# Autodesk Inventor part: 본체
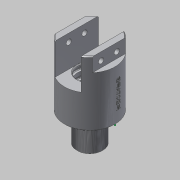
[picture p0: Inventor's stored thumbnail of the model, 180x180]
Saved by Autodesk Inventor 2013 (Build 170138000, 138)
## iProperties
Created: 2019-02
Part Number: 본체
Material: 알루미늄 6061
Document SubType Name: Modeling
Designer: Gpr
Density: 1 g/cm^3
Author: Gpr
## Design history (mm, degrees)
sketch "스케치1"
  geometry: C1 r 29 at (0, 0)
  constraints: 1 centre point
  dimensions: "d0" = 58 diameter of C1
extrude "돌출1" new body sketch "스케치1" distance "d1" = 74; taper "d2" = 0 deg
chamfer "모따기1" distance "d3" = 1; stored, may be unused: second distance "d4" = 2, angle "d5" = 45 deg
sketch "스케치2"
  geometry: C1 r 28 at (0, 0) reference; C2 r 13 at (0, 0)
  constraints: 1 centre point, 1 coincident
  dimensions: "d6" = 26 diameter of C2
extrude "돌출2" join sketch "스케치2" distance "d7" = 5; taper "d8" = 0 deg
sketch "스케치3"
  geometry: C1 r 13 at (0, 0) reference; C2 r 15 at (0, 0)
  constraints: 1 centre point, 1 coincident
  dimensions: "d9" = 30 diameter of C2
extrude "돌출3" join sketch "스케치3" distance "d10" = 28; taper "d11" = 0 deg
chamfer "모따기2" distance "d12" = 1; stored, may be unused: second distance "d13" = 2, angle "d14" = 45 deg
feature "스레드1" dims "d15" = 10, "d16" = 0
sketch "스케치4"
  geometry: L1 (-15, 29)-(15, 29); L2 (22, 29)-(22, -29); L3 (15, -29)-(-15, -29); L4 (-22, -29)-(-22, 29); L5 (15, -29)-(-15, -29); L6 (-15, -29)-(-15, 29); L7 (-15, 29)-(15, 29); L8 (15, 29)-(15, -29); L9 (22, -29)-(31.478, -29); L10 (31.478, -29)-(31.478, 29); L11 (31.478, 29)-(22, 29); L12 (22, 29)-(22, -29); L13 (-22, -29)-(-30.095, -29); L14 (-30.095, -29)-(-30.095, 29); L15 (-30.095, 29)-(-22, 29); L16 (-22, 29)-(-22, -29); 1 further point
  constraints: 32 end point, 8 parallel, 4 horizontal, 4 perpendicular, 2 midpoint
  dimensions: "d17" = 44 distance of L2.end L4.start; "d18" = 58 distance of L2.start L2.end; "d19" = 30 distance of L1.end L1.start; "d20" = 58 distance of L3.end L1.start
extrude "돌출4" cut sketch "스케치4" distance "d21" = 16; taper "d22" = 0 deg
extrude "돌출5" cut sketch "스케치4" distance "d23" = 36; taper "d24" = 0 deg
sketch "스케치5"
  geometry: L1 (0, 0)-(0, 34.641) reference; L2 (0, 0)-(9, 0); L3 (0, 0)-(9, 0); L4 (0, 17.321)-(0, 8.321); L5 (0, 17.321)-(9, 17.321); C1 r 1.322 at (9, 8.321); C2 r 2.014 at (9, 17.321); C3 r 1.322 at (9, 26.321); 1 further point
  constraints: 8 end point, 3 centre point, 2 equal length, 2 horizontal, 2 perpendicular, 1 coincident, 1 midpoint, 1 symmetric about line, 1 other
  dimensions: "d25" = 9 distance of L1.start L2.end; "d26" = 0 distance between parallel lines of L2 L3 (derived); "d27" = 9 distance of L4.start L4.end; "d28" = 90 deg angle of L4 L5 (derived)
hole "구멍1" sketch "스케치5" at (9, 26.321), (9, 8.321) diameter "d29" = 6; stored, may be unused: countersink angle "d33" = 90 deg, drill point angle "d35" = 0 deg; dims "d30" = 6, "d31" = 4, "d32" = 2, "d34" = 8
hole "구멍2" diameter "d38" = 28; stored, may be unused: countersink angle "d42" = 90 deg, drill point angle "d44" = 0 deg; dims "d39" = 6, "d40" = 28, "d41" = 2.65, "d43" = 2.65, "d80" = 10, "d81" = 10
hole "구멍3" diameter "d49" = 28; stored, may be unused: countersink angle "d53" = 90 deg, drill point angle "d55" = 0 deg; dims "d47" = 10, "d48" = 10, "d50" = 6, "d51" = 34, "d52" = 4.7, "d54" = 9
chamfer "모따기3" distance "d56" = 1; stored, may be unused: second distance "d57" = 2, angle "d58" = 45 deg
fillet "모깎기1" dims "d59" = 0.8
hole "구멍4" diameter "d62" = 28; stored, may be unused: countersink angle "d66" = 90 deg, drill point angle "d68" = 0 deg; dims "d63" = 6, "d64" = 34, "d65" = 4.7, "d67" = 8.35, "d82" = 10, "d83" = 10
fillet "모깎기2" dims "d69" = 0.8
hole "구멍5" diameter "d72" = 32; stored, may be unused: countersink angle "d76" = 90 deg, drill point angle "d78" = 0 deg; dims "d70" = 10, "d71" = 10, "d73" = 6, "d74" = 34, "d75" = 4.7, "d77" = 7
hole "구멍6" diameter "d86" = 8; stored, may be unused: countersink angle "d90" = 90 deg, drill point angle "d92" = 0 deg; dims "d84" = 10, "d85" = 10, "d87" = 6, "d88" = 34, "d89" = 4.7, "d91" = 23
chamfer "모따기4" distance "d93" = 1; stored, may be unused: second distance "d94" = 2, angle "d95" = 45 deg
hole "구멍7" diameter "d98" = 12.376; stored, may be unused: countersink angle "d102" = 90 deg, drill point angle "d104" = 0 deg; dims "d96" = 10, "d97" = 10, "d99" = 18, "d100" = 34, "d101" = 4.7, "d103" = 22
chamfer "모따기5" distance "d105" = 1; stored, may be unused: second distance "d106" = 2, angle "d107" = 45 deg
node "작업 평면2"
sketch "스케치7"
  geometry: 2 further points
  constraints: 1 other
sketch "스케치8"
  geometry: 1 further point
feature "엠보싱1" dims "d108" = 0.5, "d109" = 0
node "솔리드1"
